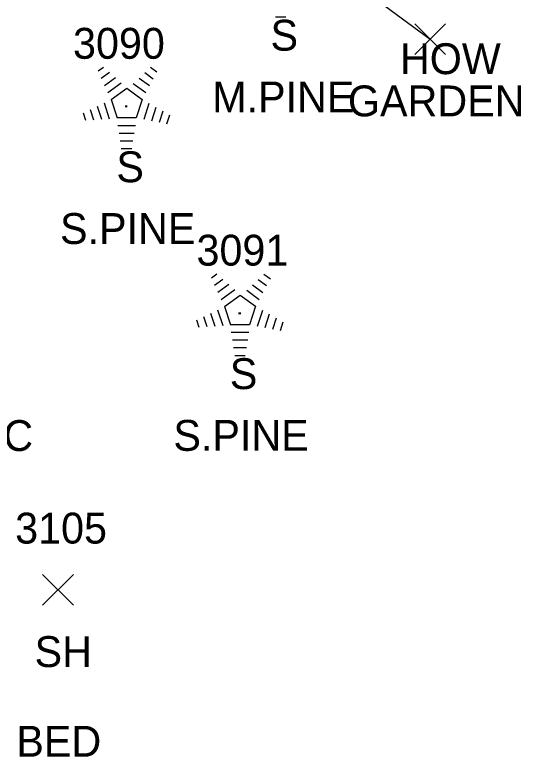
# Model space of a CAD drawing. Extents: x 1634209 to 1639641, y 608564 to 612258.
# Drawn here: x 1639021.23 to 1639054.03, y 611000.28 to 611048.37 of the extents above; entities that cross this region are included whole.
import ezdxf

# ---------------------------------------------------------------- set-up
doc = ezdxf.new("R2010")
doc.units = 0
for name, color, linetype in [('L_A', 7, 'Continuous'), ('L_C', 7, 'Continuous'), ('L_I', 7, 'Continuous'), ('L_TIC', 7, 'Continuous'), ('LAPB', 7, 'Continuous'), ('LTC', 7, 'Continuous')]:
    doc.layers.add(name, color=color, linetype=linetype)

msp = doc.modelspace()

# ---------------------------------------------------------------- linework, layer by layer
at = {"layer": 'L_TIC'}
for points in [[(1639047.14, 611045.796), (1639049.14, 611047.796)], [(1639049.14, 611045.796), (1639047.14, 611047.796)], [(1639023.022, 611010.116), (1639025.022, 611012.116)], [(1639025.022, 611010.116), (1639023.022, 611012.116)]]:
    msp.add_lwpolyline(points, dxfattribs=at)
at = {"layer": 'LAPB'}
msp.add_lwpolyline([(1639044.15, 611074.2), (1639036.346, 611067.239), (1639032.951, 611057.99), (1639048.14, 611046.796)], dxfattribs=at)
at = {"layer": 'LTC'}
for p, q in [((1639038.786, 611048.214), (1639038.111, 611048.214)), ((1639026.62, 611044.736), (1639026.975, 611044.993)), ((1639030.019, 611044.976), (1639030.438, 611044.671)), ((1639026.83, 611044.27), (1639027.359, 611044.654)), ((1639029.647, 611044.628), (1639030.197, 611044.228)), ((1639027.039, 611043.804), (1639027.743, 611044.316)), ((1639029.277, 611044.279), (1639029.956, 611043.786)), ((1639027.249, 611043.338), (1639028.127, 611043.976)), ((1639027.474, 611042.883), (1639028.485, 611043.618)), ((1639028.485, 611043.618), (1639029.482, 611042.893)), ((1639028.905, 611043.931), (1639029.715, 611043.342)), ((1639027.019, 611042.664), (1639027.35, 611041.645)), ((1639027.474, 611042.883), (1639027.861, 611041.69)), ((1639029.482, 611042.893), (1639029.091, 611041.69)), ((1639029.92, 611042.622), (1639029.582, 611041.583)), ((1639026.108, 611042.231), (1639026.32, 611041.58)), ((1639026.564, 611042.448), (1639026.835, 611041.613)), ((1639030.364, 611042.372), (1639030.077, 611041.487)), ((1639030.809, 611042.122), (1639030.572, 611041.392)), ((1639025.653, 611042.015), (1639025.805, 611041.547)), ((1639029.091, 611041.69), (1639027.861, 611041.69)), ((1639031.253, 611041.871), (1639031.066, 611041.297)), ((1639029.053, 611041.19), (1639027.908, 611041.19)), ((1639028.969, 611040.69), (1639027.981, 611040.69)), ((1639028.885, 611040.19), (1639028.054, 611040.19)), ((1639028.802, 611039.69), (1639028.127, 611039.69)), ((1639033.967, 611031.333), (1639034.321, 611031.59)), ((1639037.365, 611031.573), (1639037.784, 611031.269)), ((1639034.176, 611030.868), (1639034.706, 611031.252)), ((1639036.994, 611031.225), (1639037.544, 611030.826)), ((1639034.386, 611030.402), (1639035.09, 611030.913)), ((1639034.596, 611029.936), (1639035.474, 611030.574)), ((1639036.623, 611030.877), (1639037.302, 611030.383)), ((1639034.82, 611029.481), (1639035.832, 611030.215)), ((1639035.832, 611030.215), (1639036.829, 611029.49)), ((1639036.252, 611030.528), (1639037.061, 611029.94)), ((1639034.366, 611029.262), (1639034.696, 611028.243)), ((1639034.82, 611029.481), (1639035.207, 611028.288)), ((1639036.829, 611029.49), (1639036.438, 611028.288)), ((1639037.266, 611029.22), (1639036.929, 611028.18)), ((1639033.455, 611028.829), (1639033.666, 611028.177)), ((1639033.91, 611029.045), (1639034.181, 611028.21)), ((1639037.711, 611028.969), (1639037.424, 611028.085)), ((1639038.156, 611028.719), (1639037.919, 611027.99)), ((1639032.999, 611028.612), (1639033.151, 611028.144)), ((1639036.438, 611028.288), (1639035.207, 611028.288)), ((1639038.6, 611028.469), (1639038.413, 611027.895)), ((1639036.399, 611027.788), (1639035.255, 611027.788)), ((1639036.316, 611027.288), (1639035.327, 611027.288)), ((1639036.232, 611026.788), (1639035.4, 611026.788)), ((1639036.148, 611026.288), (1639035.473, 611026.288))]:
    msp.add_line(p, q, dxfattribs=at)

# ---------------------------------------------------------------- texts
at = {"layer": 'L_A'}
for s, p in [('S', (1639037.796, 611046.052)), ('HOW', (1639046.18, 611044.531)), ('GARDEN', (1639042.81, 611041.796)), ('S', (1639027.811, 611037.527)), ('S', (1639035.158, 611024.125)), ('SH', (1639022.51, 611006.116))]:
    msp.add_text(s, height=2, dxfattribs=at).set_placement(p)
at = {"layer": 'L_C'}
for s, p in [('M.PINE', (1639034.016, 611042.052)), ('S.PINE', (1639024.158, 611033.527)), ('LILAC', (1639014.984, 611020.114)), ('S.PINE', (1639031.504, 611020.125)), ('RAISED GARDEN BED', (1638998.443, 611000.306))]:
    msp.add_text(s, height=2, dxfattribs=at).set_placement(p)
at = {"layer": 'L_I'}
for s, p in [('3090', (1639025, 611045.527)), ('3091', (1639033, 611032.125)), ('3105', (1639021.25, 611014.116))]:
    msp.add_text(s, height=2, dxfattribs=at).set_placement(p)
at = {"layer": 'LTC'}
for p in [(1639028.368, 611042.631), (1639035.714, 611029.229)]:
    msp.add_text('.', height=1.037, rotation=270, dxfattribs=at).set_placement(p)

doc.saveas('drawing.dxf')
